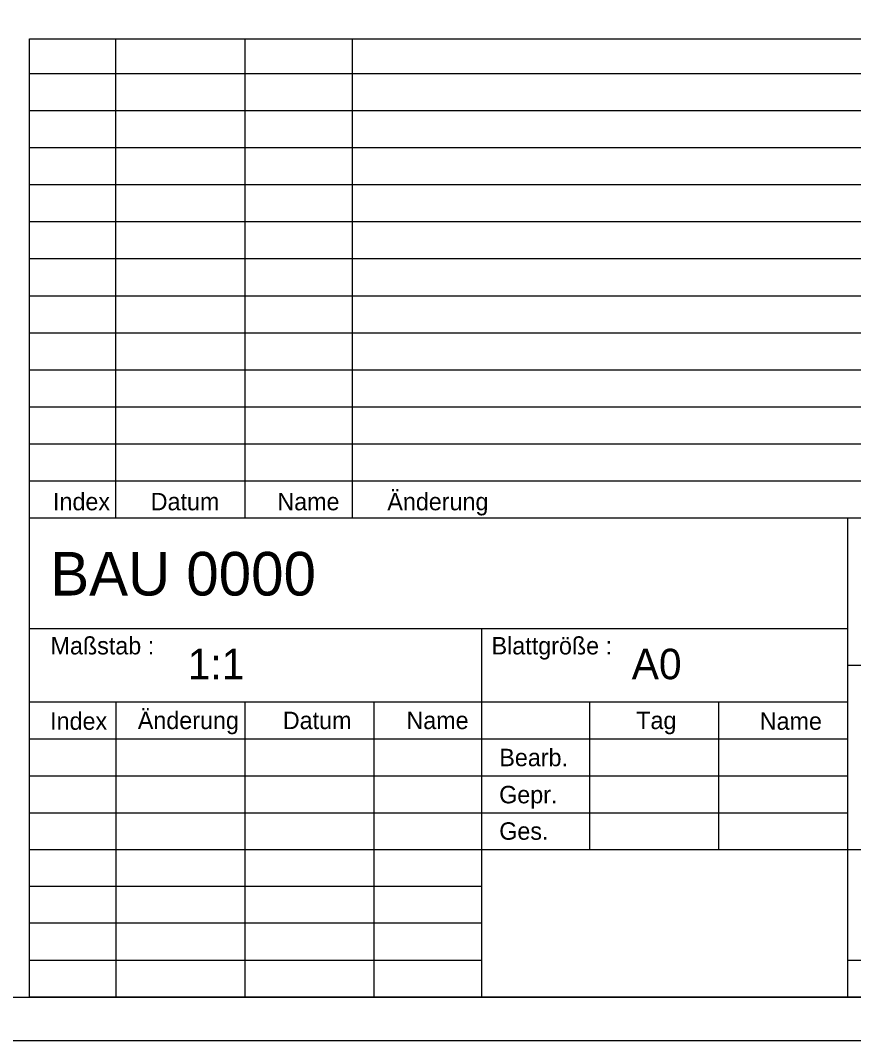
# Model space of a CAD drawing. Extents: x 0 to 1189, y 0 to 841.
# Drawn here: x 1005.1 to 1100.7, y 0 to 117.1 of the extents above; entities that cross this region are included whole.
import ezdxf

# ---------------------------------------------------------------- set-up
doc = ezdxf.new("R2010")
doc.units = 0
doc.layers.add('90_Plankopf', color=7, linetype='Continuous')

msp = doc.modelspace()

# ---------------------------------------------------------------- linework, layer by layer
at = {"layer": '90_Plankopf'}
for p, q in [((1006.12, 59.99), (1006.12, 114.98)), ((1006.12, 114.98), (1184, 114.98)), ((1016, 59.99), (1016, 114.98)), ((1030.83, 59.99), (1030.83, 114.98)), ((1043.18, 59.99), (1043.18, 114.98)), ((1006.12, 110.99), (1184, 110.99)), ((1006.12, 106.74), (1184, 106.74)), ((1006.12, 102.49), (1184, 102.49)), ((1006.12, 98.24), (1184, 98.24)), ((1006.12, 93.99), (1184, 93.99)), ((1006.12, 89.74), (1184, 89.74)), ((1006.12, 85.49), (1184, 85.49)), ((1006.12, 81.24), (1184, 81.24)), ((1006.12, 76.99), (1184, 76.99)), ((1006.12, 72.74), (1184, 72.74)), ((1006.12, 68.49), (1184, 68.49)), ((1006.12, 64.24), (1184, 64.24)), ((1006.12, 59.99), (1184, 59.99)), ((1006.12, 5), (1006.12, 59.99)), ((1006.12, 59.99), (1184, 59.99)), ((1100, 5), (1100, 59.99)), ((1006.12, 47.3), (1100, 47.3)), ((1058, 5), (1058, 47.3)), ((1100, 43.07), (1184, 43.07)), ((1006.12, 38.87), (1100, 38.87)), ((1016, 38.84), (1016, 5)), ((1030.83, 5), (1030.83, 38.84)), ((1045.65, 5), (1045.65, 38.84)), ((1070.35, 38.84), (1070.35, 21.92)), ((1085.18, 21.92), (1085.18, 38.84)), ((1006.12, 34.63), (1100, 34.63)), ((1006.12, 30.38), (1100, 30.38)), ((1006.12, 26.15), (1100, 26.15)), ((1006.12, 21.92), (1100, 21.92)), ((1006.12, 21.92), (1100, 21.92)), ((1058, 21.92), (1100, 21.92)), ((1100, 21.92), (1184, 21.92)), ((1058, 17.69), (1006.12, 17.69)), ((1058, 13.46), (1006.12, 13.46)), ((1006.12, 9.23), (1058, 9.23)), ((1100, 9.23), (1184, 9.23)), ((1184, 5), (1006.12, 5)), ((1006.12, 5), (1058, 5)), ((1017.8, 5), (1184, 5)), ((1017.8, 5), (1184, 5))]:
    msp.add_line(p, q, dxfattribs=at)
for points in [[(0, 0), (1189, 0), (1189, 841), (0, 841)], [(25, 5), (1184, 5), (1184, 836), (25, 836)]]:
    msp.add_lwpolyline(points, close=True, dxfattribs=at)

# ---------------------------------------------------------------- texts
for s, height, p in [('Änderung', 2, (1047.16, 60.86)), ('Index', 2, (1008.8, 60.86)), ('Datum', 2, (1020.01, 60.86)), ('Name', 2, (1034.54, 60.86)), ('BAU 0000      ', 5, (1008.49, 51.08)), ('Maßstab :', 2, (1008.52, 44.32)), ('Blattgröße :', 1.9999, (1059.12, 44.32)), ('1:1      ', 3.5, (1024.26, 41.47)), ('A0       ', 3.5, (1075.2, 41.47)), ('Index', 2, (1008.47, 35.67)), ('Änderung', 2, (1018.53, 35.75)), ('Datum', 2, (1035.17, 35.75)), ('Name', 2, (1049.35, 35.75)), ('Tag', 2, (1075.72, 35.75)), ('Name', 2, (1089.89, 35.67)), ('Bearb.', 2, (1060.01, 31.49)), ('Gepr.', 2, (1059.99, 27.23)), ('Ges.', 2, (1060, 23.05))]:
    msp.add_text(s, height=height, dxfattribs=at).set_placement(p)

doc.saveas('drawing.dxf')
